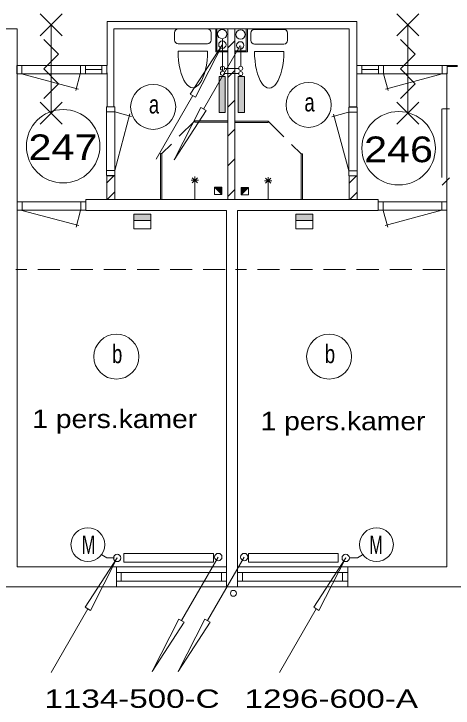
# Model space of a CAD drawing. Extents: x 295824 to 414724, y 24924 to 109024.
# Drawn here: x 308047 to 314024, y 85900 to 95351 of the extents above; entities that cross this region are included whole.
import ezdxf
from ezdxf.enums import TextEntityAlignment as Align

# ---------------------------------------------------------------- set-up
doc = ezdxf.new("R2010")
doc.units = 0
doc.header["$LTSCALE"] = 100
doc.linetypes.add('LONG_DASHED', pattern=[7.5, 6, -1.5])
doc.linetypes.add('MEDIUM_DASHED', pattern=[4.5, 3, -1.5])
doc.layers.add('16', color=7, linetype='Continuous', lineweight=13)
doc.layers.add('61', color=7, linetype='Continuous', lineweight=13)

msp = doc.modelspace()

# ---------------------------------------------------------------- hatches: boundary and pattern name
at = {"layer": '16'}
for points in [[(310838.6, 94007.6), (310924, 94007.6), (310924, 94499.8), (310838.6, 94499.8)], [(311097.8, 94007.6), (311183.2, 94007.6), (311183.2, 94499.8), (311097.8, 94499.8)], [(309911.3, 92624.5), (309679.8, 92624.5), (309679.8, 92538), (309911.3, 92538)], [(312117.3, 92624.5), (311885.8, 92624.5), (311885.8, 92538), (312117.3, 92538)]]:
    msp.add_hatch(color=256, dxfattribs=at).paths.add_polyline_path(points)
at = {"layer": '61'}
for points in [[(310777.4, 92991.3), (310877.4, 92891.3), (310877.4, 92991.3)], [(311239.9, 92985.9), (311139.9, 92885.9), (311139.9, 92985.9)]]:
    msp.add_hatch(color=256, dxfattribs=at).paths.add_polyline_path(points)

# ---------------------------------------------------------------- linework, layer by layer
at = {"layer": '16'}
for p, q in [((310885.9, 95010.5), (310885.9, 94574)), ((311127.8, 94922.2), (310627.8, 94056.2)), ((311106.2, 94538.6), (310914.5, 94538.6)), ((309983.9, 93373.3), (310483.9, 94239.3)), ((309679.8, 92538), (309679.8, 92424.1)), ((311885.8, 92538), (311885.8, 92424.1)), ((310828.9, 87956.8), (310328.9, 87090.8)), ((311182.3, 87956.8), (310682.3, 87090.8)), ((308552.5, 86385.7), (309052.5, 87251.7)), ((311662.7, 86385.7), (312162.7, 87251.7))]:
    msp.add_line(p, q, dxfattribs=at)
at = {"layer": '16', "linetype": 'LONG_DASHED'}
for p, q in [((311137.1, 94906.7), (311137.1, 94635.1)), ((310914.6, 94609.4), (311106.1, 94609.4))]:
    msp.add_line(p, q, dxfattribs=at)
at = {"layer": '16'}
for points in [[(310883.9, 94932.3), (310519.9, 94218.3), (310447.9, 94260.3)], [(310838.6, 94007.6), (310924, 94007.6), (310924, 94499.8), (310838.6, 94499.8)], [(311097.8, 94007.6), (311183.2, 94007.6), (311183.2, 94499.8), (311097.8, 94499.8)], [(310227.8, 93363.2), (310591.8, 94077.2), (310663.8, 94035.2)], [(309911.3, 92624.5), (309679.8, 92624.5), (309679.8, 92538), (309911.3, 92538)], [(312117.3, 92624.5), (311885.8, 92624.5), (311885.8, 92538), (312117.3, 92538)], [(309542.9, 88006.2), (310762.2, 88006.2), (310762.2, 87888.3), (309542.9, 87888.3)], [(311241.8, 88006.2), (312461.2, 88006.2), (312461.2, 87888.3), (311241.8, 87888.3)], [(309452.5, 87944.7), (309088.5, 87230.7), (309016.5, 87272.7)], [(312562.7, 87944.7), (312198.7, 87230.7), (312126.7, 87272.7)], [(309928.9, 86397.8), (310292.9, 87111.8), (310364.9, 87069.8)], [(310282.3, 86397.8), (310646.3, 87111.8), (310718.3, 87069.8)]]:
    msp.add_lwpolyline(points, close=True, dxfattribs=at)
for points in [[(309911.3, 92538), (309911.3, 92424.1), (309679.8, 92424.1)], [(312117.3, 92538), (312117.3, 92424.1), (311885.8, 92424.1)], [(309414.8, 87947.9), (309312.2, 87947.9), (309245.8, 87986.3)], [(312620.4, 87947.9), (312722.9, 87947.9), (312789.4, 87986.3)]]:
    msp.add_lwpolyline(points, dxfattribs=at)
for centre, radius in [((310883.9, 94932), 50), ((311127.8, 94922.6), 50), ((310886.7, 94609.4), 27.9), ((311134.1, 94609.4), 27.9), ((310886.7, 94541.6), 27.9), ((311134.1, 94538.6), 27.9), ((309054.2, 88125.9), 229.9), ((312980.9, 88125.9), 229.9), ((309452.5, 87944.4), 50), ((310828.9, 87957.1), 50), ((311182.3, 87957.1), 50), ((312562.7, 87944.4), 50)]:
    msp.add_circle(centre, radius, dxfattribs=at)
at = {"layer": '61'}
for p, q in [((308402.5, 95051.1), (308702.5, 95351.1)), ((308702.5, 95051.1), (308402.5, 95351.1)), ((313258.4, 95051.1), (313558.4, 95351.1)), ((313558.4, 95051.1), (313258.4, 95351.1)), ((308552.5, 95201.1), (308552.5, 94001.1)), ((313408.4, 95201.1), (313408.4, 94001.1)), ((308090.1, 95148.4), (308090.1, 87823.4)), ((309409.2, 94086.3), (309409.2, 95148.4)), ((310232.4, 94995.4), (310232.4, 95095.4)), ((310282.4, 95145.4), (310682.4, 95145.4)), ((310732.4, 95095.4), (310732.4, 94995.4)), ((310809.2, 94848.4), (310809.2, 95148.4)), ((310959.2, 92823.4), (310959.2, 95148.4)), ((311055.5, 92823.4), (311055.5, 95148.4)), ((311209.3, 95147.9), (311209.3, 94847.9)), ((311271.8, 94990.5), (311271.8, 95090.5)), ((311321.8, 95140.5), (311721.8, 95140.5)), ((311771.8, 95090.5), (311771.8, 94990.5)), ((311054.9, 94982.4), (310959.2, 94886.7)), ((310682.4, 94945.4), (310282.4, 94945.4)), ((311721.8, 94940.5), (311321.8, 94940.5)), ((310282.4, 94845.4), (310682.4, 94845.4)), ((310959.2, 94848.4), (310809.2, 94848.4)), ((311209.3, 94847.9), (311059.3, 94847.9)), ((311321.8, 94840.5), (311721.8, 94840.5)), ((308153, 94648.3), (308153, 94534.3)), ((308953, 94648.3), (308953, 94534.3)), ((309020, 94648.3), (309020, 94534.3)), ((309246, 94648.3), (309246, 94534.3)), ((312714.4, 94084.9), (312714.4, 94650.7)), ((312782.6, 94648.3), (312782.6, 94534.3)), ((313008.6, 94648.3), (313008.6, 94534.3)), ((313075.6, 94648.3), (313075.6, 94534.3)), ((313875.6, 94648.3), (313875.6, 94534.3)), ((313944.8, 94648.3), (314086, 94648.3)), ((313944.8, 94633.3), (314086, 94633.3)), ((308152.2, 94533.7), (308925, 94326.6)), ((308950.6, 94533.1), (308889.9, 94306.2)), ((309246, 94594.2), (309020, 94594.2)), ((309314.4, 94086.3), (309314.4, 94548.4)), ((311054.9, 94581.5), (310959.2, 94485.8)), ((312782.6, 94594.2), (313008.6, 94594.2)), ((313078, 94533.1), (313138.7, 94306.2)), ((313876.4, 94533.7), (313103.6, 94326.6)), ((313940.1, 94548.4), (313940.1, 87823.4)), ((308402.5, 93851.1), (308702.5, 94151.1)), ((308702.5, 93851.1), (308402.5, 94151.1)), ((311054.9, 94178.2), (310959.2, 94082.4)), ((313258.4, 93851.1), (313558.4, 94151.1)), ((313558.4, 93851.1), (313258.4, 94151.1)), ((309306.9, 93151.5), (309306.9, 94085.5)), ((309409.2, 94086.3), (309314.4, 94086.3)), ((312714.4, 94084.9), (312609.2, 94084.9)), ((312720.4, 93148.9), (312720.4, 94081.3)), ((313872.9, 93123.7), (313872.9, 94057.7)), ((313975.1, 94058.5), (313880.4, 94058.5)), ((309306.9, 94018.5), (309420.9, 94018.5)), ((309419, 93217.8), (309626, 93990.5)), ((309419.6, 94016.2), (309646.5, 93955.4)), ((312602.6, 94011.9), (312375.7, 93951.2)), ((312603.2, 93213.5), (312396.2, 93986.3)), ((312720.4, 94014.3), (312606.4, 94014.3)), ((310960.3, 93897), (310510.8, 93897)), ((310510.8, 93897), (310510.8, 93879)), ((310960, 93879), (310510.8, 93879)), ((311057, 93891.6), (311506.5, 93891.6)), ((311057.3, 93873.6), (311506.5, 93873.6)), ((311506.5, 93891.6), (311506.5, 93873.6)), ((311054.9, 93782.2), (310959.2, 93686.4)), ((310059.9, 92829), (310059.9, 93449.5)), ((311054.9, 93377.6), (310959.2, 93281.8)), ((311957.4, 92823.6), (311957.4, 93444.1)), ((309306.9, 93218.5), (309420.9, 93218.5)), ((312720.4, 93214.3), (312606.4, 93214.3)), ((309420.3, 93151.5), (309306.3, 93151.5)), ((309409.3, 93146.8), (309309.6, 93047.1)), ((309419.6, 93148), (309309.7, 93148)), ((309309.7, 93148), (309309.7, 92823.9)), ((309419.6, 93148), (309419.6, 92823.9)), ((310545.2, 93050.1), (310474.4, 93120.8)), ((310545.2, 93120.8), (310474.4, 93050.1)), ((310509.8, 93035.5), (310509.8, 93135.5)), ((311472.1, 93044.8), (311542.9, 93115.5)), ((311472.1, 93115.5), (311542.9, 93044.8)), ((311507.5, 93030.1), (311507.5, 93130.1)), ((312707.8, 93146.8), (312608.1, 93047.1)), ((312718.6, 93148), (312608.6, 93148)), ((312608.6, 93148), (312608.6, 92823.9)), ((312718.6, 93148), (312718.6, 92823.9)), ((313975.2, 93118.9), (313875.5, 93019.2)), ((310559.8, 93085.5), (310459.8, 93085.5)), ((310509.8, 93035.5), (310509.8, 92835.5)), ((311457.5, 93080.1), (311557.5, 93080.1)), ((311507.5, 93030.1), (311507.5, 92830.1)), ((309417.9, 92924.2), (309318.2, 92824.5)), ((311054.9, 92959.5), (310959.2, 92863.7)), ((312720.1, 92924.2), (312620.4, 92824.5)), ((309419.6, 92823.9), (309309.7, 92823.9)), ((312718.6, 92823.9), (312608.6, 92823.9)), ((308157.6, 92790.9), (308157.6, 92676.9)), ((308957.6, 92790.9), (308957.6, 92676.9)), ((309024.6, 92790.9), (309024.6, 92676.9)), ((313005.2, 92791.9), (313005.2, 92677.9)), ((313072.2, 92791.9), (313072.2, 92677.9)), ((313872.2, 92791.9), (313872.2, 92677.9)), ((308156.8, 92676.2), (308929.5, 92469.2)), ((308955.2, 92675.6), (308894.4, 92448.8)), ((310940.1, 87553.8), (310940.1, 92673.4)), ((311090.1, 87553.8), (311090.1, 92673.4)), ((313074.6, 92676.7), (313135.4, 92449.8)), ((313873, 92677.3), (313100.3, 92470.3)), ((308090.1, 87823.4), (310940.1, 87823.4)), ((309441.5, 87552.2), (309441.5, 87822.2)), ((313940.1, 87823.4), (311090.1, 87823.4)), ((312589.8, 87552.2), (312589.8, 87821.5)), ((309508.3, 87630.5), (309508.3, 87744.3)), ((310873.3, 87629.9), (310873.3, 87743.9)), ((311156.8, 87630.8), (311156.8, 87744.8)), ((312521.1, 87630.5), (312521.1, 87744.2)), ((326233, 87553.4), (307806, 87553.4))]:
    msp.add_line(p, q, dxfattribs=at)
at = {"layer": '61', "linetype": 'MEDIUM_DASHED'}
for p, q in [((310508.8, 93896.5), (310061.9, 93449.6)), ((311508.5, 93891.2), (311955.4, 93444.3)), ((310922.5, 91870), (308075.5, 91870)), ((313911.6, 91870), (311064.6, 91870))]:
    msp.add_line(p, q, dxfattribs=at)
at = {"layer": '61'}
for points in [[(312714.4, 94648.4), (312714.4, 95248.4), (309314.4, 95248.4), (309314.4, 94648.4)], [(308090.1, 95148.4), (307832.8, 95148.4), (307832.8, 94654.5)], [(312609.2, 94084.9), (312609.2, 95148.4), (309409.2, 95148.4)], [(310959.2, 94833.4), (310794.2, 94833.4), (310794.2, 95148.4)], [(311224.3, 95147.9), (311224.3, 94832.9), (311059.3, 94832.9)], [(308452.5, 95001.1), (308652.5, 94801.1), (308452.5, 94601.1), (308652.5, 94401.1), (308452.5, 94201.1)], [(313308.4, 95001.1), (313508.4, 94801.1), (313308.4, 94601.1), (313508.4, 94401.1), (313308.4, 94201.1)], [(310041.9, 92829), (310041.9, 93449.5), (310059.9, 93449.5)], [(311975.4, 92823.6), (311975.4, 93444.1), (311957.4, 93444.1)], [(310877.4, 92891.3), (310877.4, 92991.3), (310777.4, 92991.3)], [(311139.9, 92885.9), (311139.9, 92985.9), (311239.9, 92985.9)], [(311089.4, 92673.4), (313004.4, 92673.4), (313004.4, 92823.4), (309025.1, 92823.4)], [(310939.4, 92673.4), (309025.1, 92673.4), (309025.1, 92823.4)], [(308090.6, 92790.9), (308090.6, 92676.9), (309024.6, 92676.9)], [(309024.6, 92790.9), (308090.6, 92790.9), (308090.6, 92676.9)], [(313939.2, 92791.9), (313939.2, 92677.9), (313005.2, 92677.9)], [(313005.2, 92791.9), (313939.2, 92791.9), (313939.2, 92677.9)]]:
    msp.add_lwpolyline(points, dxfattribs=at)
for points in [[(309313, 94648.3), (309313, 94534.3), (308086, 94534.3), (308086, 94648.3)], [(309313, 94648.3), (309313, 94534.3), (308086, 94534.3), (308086, 94648.3)], [(313942.6, 94648.3), (313942.6, 94534.3), (312716.2, 94534.3), (312716.2, 94648.3)], [(313942.6, 94648.3), (313942.6, 94534.3), (312716.2, 94534.3), (312716.2, 94648.3)], [(309306.9, 93151.5), (309306.9, 94085.5), (309420.9, 94085.5), (309420.9, 93151.5)], [(312720.4, 94082.2), (312606.4, 94082.2), (312606.4, 93148.2), (312720.4, 93148.2)], [(310877.4, 92891.3), (310777.4, 92891.3), (310777.4, 92991.3)], [(310777.4, 92991.3), (310877.4, 92891.3), (310877.4, 92991.3)], [(311139.9, 92885.9), (311239.9, 92885.9), (311239.9, 92985.9)], [(311239.9, 92985.9), (311139.9, 92885.9), (311139.9, 92985.9)], [(309441.5, 87630.3), (309441.5, 87744.3), (310940.1, 87744.3), (310940.1, 87630.3)], [(311090.5, 87630.5), (311090.5, 87744.5), (312589.8, 87744.5), (312589.8, 87630.5)]]:
    msp.add_lwpolyline(points, close=True, dxfattribs=at)
for centre, radius in [((310881.7, 95075.9), 62.5), ((311131.7, 95070.4), 62.5), ((312058.4, 94112.4), 306.3), ((309942.5, 94084.5), 306.3), ((308717.2, 93549.6), 500), ((313283.2, 93521.8), 500), ((309441.3, 90685.4), 306.3), ((312336.8, 90685.4), 306.3), ((311034.3, 87463.3), 40)]:
    msp.add_circle(centre, radius, dxfattribs=at)
for centre, start, end in [((310282.4, 95095.4), 90, 180), ((310682.4, 95095.4), 0, 90), ((311321.8, 95090.5), 90, 180), ((311721.8, 95090.5), 0, 90), ((310282.4, 94995.4), 180, 270), ((310682.4, 94995.4), 270, 0), ((311321.8, 94990.5), 180, 270), ((311721.8, 94990.5), 270, 0)]:
    msp.add_arc(centre, 50, start, end, dxfattribs=at)
for centre in [(310482.4, 94845.4), (311521.8, 94840.5)]:
    msp.add_ellipse(centre, major_axis=(0, -500), ratio=0.4, start_param=4.712389, end_param=7.853982, dxfattribs=at)

# ---------------------------------------------------------------- texts
at = {"layer": '16'}
for s, width, p in [('M', 0.65, (308972, 87999.3)), ('M', 0.65, (312886, 87999.3)), ('1134-500-C', 1.35, (308462.8, 85903.8)), ('1296-600-A', 1.35, (311187, 85903.8))]:
    msp.add_text(s, height=250, dxfattribs=dict(at, width=width)).set_placement(p)
at = {"layer": '61'}
for s, width, p in [('a', 0.75, (309884.5, 93995.3)), ('a', 0.75, (312000.4, 94023.2)), ('b', 0.75, (309383.3, 90596.2)), ('b', 0.75, (312278.8, 90596.2)), ('1 pers.kamer', 1.15, (308297.8, 89713.2)), ('1 pers.kamer', 1.15, (311404.3, 89683.7))]:
    msp.add_text(s, height=250, dxfattribs=dict(at, width=width)).set_placement(p)
at = {"layer": '61', "width": 1.2}
for s, p in [('247', (308714.3, 93359.8)), ('246', (313281.6, 93331.9))]:
    msp.add_text(s, height=350, dxfattribs=at).set_placement(p, align=Align.CENTER)

doc.saveas('drawing.dxf')
